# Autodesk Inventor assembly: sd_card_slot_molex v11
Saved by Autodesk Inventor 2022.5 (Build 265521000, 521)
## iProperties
Created: 2024-12
Part Number: sd_card_slot_molex v11
Document SubType Name: Assembly
Designer: AdminForWorker
Title: sd_card_slot_molex v11
Author: AdminForWorker
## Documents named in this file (4)
- c:\worker\convert-fusion-r05-cosv3\tmp\job-1\35\temp\files\545dca92-a972-481a-9197-dd1a1176500e\sd_card_slot_molex v11.iam
- c:\worker\convert-fusion-r05-cosv3\tmp\job-1\35\temp\files\545dca92-a972-481a-9197-dd1a1176500e\housing.iam
- c:\worker\convert-fusion-r05-cosv3\tmp\job-1\35\temp\files\545dca92-a972-481a-9197-dd1a1176500e\base.ipt
- c:\worker\convert-fusion-r05-cosv3\tmp\job-1\35\temp\files\545dca92-a972-481a-9197-dd1a1176500e\leads.iam
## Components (3 placed, 3 different names)
1. housing:1 [sub-assembly]
2. base:1
3. leads:1 [sub-assembly]
